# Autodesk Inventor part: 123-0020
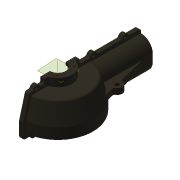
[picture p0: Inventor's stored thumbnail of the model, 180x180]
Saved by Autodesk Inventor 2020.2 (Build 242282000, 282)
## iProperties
Created: 2006-02
Part Number: 123-0020
Document SubType Name: Modeling
Designer: F.Stasiak
Description: Obudowa - lewa
Material: L450
Project: Przekładnia X51
Mass: 3379.48 g
Surface Area: 1383.43 cm^2
Volume: 466.135 cm^3
Density: 7.25 g/cm^3
Appearance: Brąz armatni (nowy/polerowany)
Manager: www.cadconsulting.pl
Company: Fabian Stasiak CAD Consulting
Author: F.Stasiak
Subject: Zbiór ćwiczeń. Autodesk Inventor 2020. Kurs podstawowy
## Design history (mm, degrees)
derived "123-0010.ipt"
  node "Płaszczyzna konstrukcyjna1"
  node "Płaszczyzna konstrukcyjna2"
  node "Płaszczyzna konstrukcyjna4"
  node "Oś konstrukcyjna1"
node "Bryła1"
node "Korpusy bryłowe"
node "Korpusy powierzchniowe"
tag "Bryła wyprowadzona2"
node "Płaszczyzna konstrukcyjna5"
node "Płaszczyzna konstrukcyjna3"
feature "DerivedBody::123-0010.ipt"
